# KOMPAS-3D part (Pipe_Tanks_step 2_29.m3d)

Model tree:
1. X Axis
2. Y Axis
3. Z Axis  (labels: Pipe Dn 50)
     Òîëùèíà ñòåíêè 1 = 1

Referenced files in C:\Documents and Settings\kashirsky\Мои документы\Camtasia Studio\Pipelines3D\Tanks\: Tanks_step 2.a3d
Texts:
  Pipe Dn 50
  Steel ASTM A295
  Three Point Plane
  Plane at Angle
  Line and Point Plane
  Axis through Two Vertices
  Axis of Feature
  Axis of Conical Surface
  Axis through Edge
  Trim by Surface
  Trim by Sketch
  Feature with No History
  Intersection Axis of Two Planes
  Two Line Plane
  Line and Face Plane
  Bend by line
  Hole in sheet body
  Cut in sheet body
  Point in CM
  Linear Dimension from Line to Point
  Surface Finish Symbol
  Geometric Tolerance Symbol
  Leader #1
  Leader #2
  Leader #3
  Shape Deviations and Datum
  Node point number
  Mark of coordination axis
  Node point designation
  Mark/Reference designation with leader
  Mark/reference designation on line
  Mark/Reference designation without leader
  Plane of section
